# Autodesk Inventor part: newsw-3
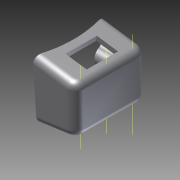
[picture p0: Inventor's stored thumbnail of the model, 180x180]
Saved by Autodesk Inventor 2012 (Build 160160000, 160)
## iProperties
Created: 2013-04
Part Number: newsw-3
Material: Default
Document SubType Name: Modeling
Designer: Norm
Density: 1 g/cm^3
Author: Norm
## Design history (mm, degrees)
sketch "Sketch1"
  geometry: L1 (-2.815, 6.111)-(15.185, 6.111); L2 (15.185, 6.111)-(15.185, -23.889); L3 (15.185, -23.889)-(-2.815, -23.889); L4 (-2.815, -23.889)-(-2.815, 6.111); 1 further point
  constraints: 8 end point, 2 parallel, 1 horizontal, 1 perpendicular
  dimensions: "d0" = 18 distance of L1.start L1.end; "d1" = 30 distance of L1.end L2.end
extrude "Extrusion1" new body sketch "Sketch1" distance "d2" = 22; taper "d3" = 0 deg
feature "FaceDraft1" dims angle "d4" = -8 deg
fillet "Fillet1" dims "d5" = 4
fillet "Fillet2" dims "d6" = 3
shell "Shell1" dims "d7" = 2
sketch "Sketch2"
  geometry: L1 (2.02, 0)-(2.02, 24) reference; L2 (3.029, 25)-(21.5, 25) reference; L3 (22.51, 24)-(22.51, 0) reference; L4 (21.5, -1)-(3.029, -1) reference; L5 (12.265, 25)-(12.265, -1); L6 (22.51, 12)-(2.02, 12); C1 r 3 at (12.265, 23.629); C2 r 3 at (12.265, 0.371); 3 further points
  constraints: 4 end point, 4 midpoint, 2 centre point, 2 coincident, 1 point on line, 1 symmetric about line, 1 other
  dimensions: "d8" = 6 diameter of C1
sketch "Sketch10"
  geometry: L1 (-10.16, 4.425)-(-1.16, 4.425); L2 (-1.16, 4.425)-(-1.16, 17.575); L3 (-1.16, 17.575)-(-10.16, 17.575); L4 (-10.16, 17.575)-(-10.16, 4.425); L5 (-1.01, -1)-(-15.569, -1) reference; L6 (-15.569, 23)-(-1.01, 23) reference; L7 (-12.777, 23)-(-12.777, -1); 7 further points; 1 other entity
  constraints: 10 end point, 2 horizontal alignment, 2 midpoint, 2 parallel, 2 perpendicular, 2 point on line, 1 horizontal, 2 other
  dimensions: "d28" = 13.15 distance of L3.end L1.start; "d29" = 9 distance of L2.end L3.end
extrude "Extrusion6" cut sketch "Sketch10" distance "d30" = 2.1; taper "d31" = 0 deg
extrude "Extrusion7" join sketch "Sketch2" stored distance "d32" = 0; taper "d33" = 0 deg
sketch "Sketch11"
  geometry: A1 r 3 centre (12.265, 23.629) between (9.596, 25) and (14.933, 25) reference; A2 r 3 centre (12.265, 0.371) between (14.933, -1) and (9.596, -1) reference; 3 further points
  constraints: 2 coincident
hole "Hole1" sketch "Sketch11" at (12.265, 23.629), (12.265, 0.371) diameter "d34" = 1; stored, may be unused: countersink angle "d38" = 90 deg, drill point angle "d40" = 118 deg; dims "d35" = 6, "d36" = 4, "d37" = 2, "d39" = 3
fillet "Fillet4" dims "d41" = 2
workaxis "Work Axis1"
workaxis "Work Axis2"
workpoint "Work Point1"
workpoint "Work Point2"
workplane "Work Plane7"
  workaxis "Work Axis3"
sketch "Sketch12"
  geometry: L1 (22.127, -65)-(-7.873, -65); L2 (-7.873, -65)-(-7.873, -118); L3 (-7.873, -118)-(22.127, -116); L4 (22.127, -116)-(22.127, -65); L5 (-2.108, -16)-(16.363, -16) reference; L6 (10.636, -16)-(10.636, -65); 3 further points
  constraints: 10 end point, 3 perpendicular, 2 midpoint, 2 point on line, 1 horizontal, 1 parallel, 1 vertical alignment
  dimensions: "d43" = 53 distance of L1.end L2.end; "d44" = 51 distance of L3.end L1.start; "d45" = 30 distance of L1.start L1.end; "d47" = 49 distance of L6.start L6.end
revolve "Revolution1" sketch "Sketch12" stored, may be unused: angle "d48" = 90 deg
body "Solid1"
other parameters: "d42" = 90 deg
